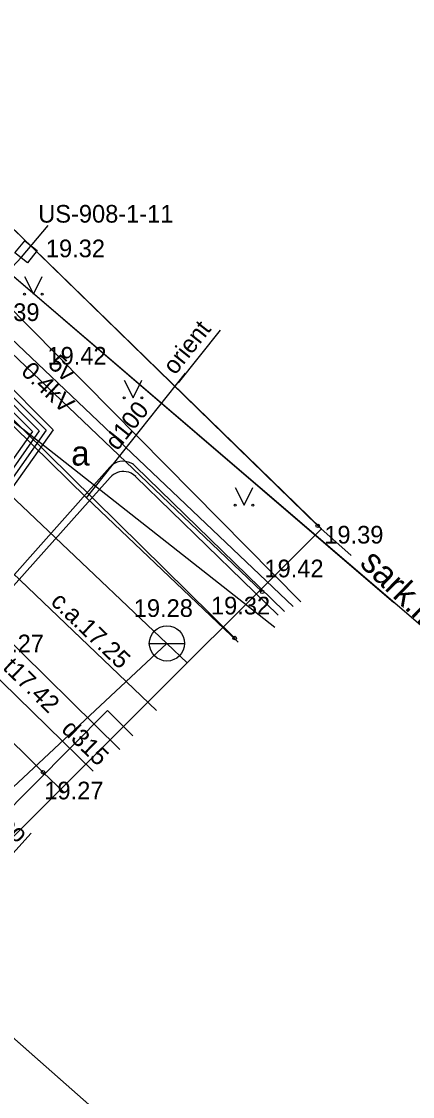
# Model space of a CAD drawing. Extents: x 532933 to 533143, y 328014 to 328163.
# Drawn here: x 533036.51 to 533047.57, y 328096.56 to 328126.98 of the extents above; entities that cross this region are included whole.
import ezdxf

# ---------------------------------------------------------------- set-up
doc = ezdxf.new("R2010")
doc.units = 0
for name, color, linetype in [('APGR_SARK_####_####_#', 7, 'Continuous'), ('APGR_SARK_####_TKST_#', 7, 'Continuous'), ('APGS_VADV_ZSPR_####_#', 7, 'Continuous'), ('APGS_VADV_ZSPR_TKST_#', 7, 'Continuous'), ('CELI_CAPM_####_####_#', 7, 'Continuous'), ('CELI_CMAL_####_####_#', 7, 'Continuous'), ('CELI_CSEG_####_TKST_#', 7, 'Continuous'), ('ELEK_ELEM_####_####_#', 7, 'Continuous'), ('ELEK_ELEM_####_TKST_#', 7, 'Continuous'), ('ELEK_VADP_ZSPR_####_#', 7, 'Continuous'), ('LKAN_ELEM_PAST_TKST_#', 7, 'Continuous'), ('LKAN_VADP_PAST_####_#', 7, 'Continuous'), ('LKAN_VADP_PAST_TKST_#', 7, 'Continuous'), ('NORB_ZOGS_KOKA_####_#', 7, 'Continuous'), ('NORB_ZOGS_ZSTP_####_#', 7, 'Continuous'), ('RAMI_UZMR_####_####_#', 7, 'Continuous'), ('RELJ_AATZ_####_TKST_#', 7, 'Continuous'), ('RELJ_ELEM_####_####_#', 7, 'Continuous'), ('ROBZ_PROJ_####_####_#', 7, 'Continuous'), ('ROBZ_UZMR_####_####_#', 7, 'Continuous'), ('SAKK_IZVK_####_TKST_#', 7, 'Continuous'), ('SAKT_VADP_KABE_####_#', 7, 'Continuous'), ('SAKT_VADV_PKAB_####_#', 7, 'Continuous'), ('SKAN_VADP_PAST_####_#', 7, 'Continuous'), ('TERT_ELEM_####_####_#', 7, 'Continuous'), ('UDTK_ELEM_####_####_#', 7, 'Continuous'), ('UDTK_ELEM_####_TKST_#', 7, 'Continuous'), ('UDTK_VADP_UDEN_####_#', 7, 'Continuous'), ('UDTK_VADP_UDEN_TKST_#', 7, 'Continuous')]:
    doc.layers.add(name, color=color, linetype=linetype)

msp = doc.modelspace()

# ---------------------------------------------------------------- linework, layer by layer
at = {"layer": 'APGR_SARK_####_####_#'}
msp.add_line((533031.763, 328123.637), (533047.049, 328110.542), dxfattribs=at)
at = {"layer": 'APGS_VADV_ZSPR_####_#'}
msp.add_line((533035.157, 328119.006), (533044.195, 328110.43), dxfattribs=at)
at = {"layer": 'CELI_CAPM_####_####_#'}
for points in [[(533042.54, 328109.533), (533031.272, 328120.63), (533030.925, 328121.836)], [(533031.218, 328107.846), (533032.06, 328108.202), (533033.785, 328108.244), (533035.723, 328107.108), (533037.113, 328105.736)], [(533037.113, 328105.736), (533037.712, 328105.165)]]:
    msp.add_lwpolyline(points, dxfattribs=at)
at = {"layer": 'CELI_CMAL_####_####_#'}
msp.add_lwpolyline([(533032.509, 328123.107), (533032.012, 328121.984), (533033.169, 328120.513), (533043.316, 328110.84)], dxfattribs=at)
at = {"layer": 'ELEK_ELEM_####_####_#'}
msp.add_lwpolyline([(533036.673, 328120.155), (533036.322, 328120.433), (533036.596, 328120.778), (533036.946, 328120.5)], close=True, dxfattribs=at)
at = {"layer": 'ELEK_VADP_ZSPR_####_#'}
for p, q in [((533021.678, 328131.149), (533037.401, 328115.43)), ((533021.501, 328130.901), (533037.01, 328115.397)), ((533021.59, 328131.025), (533037.205, 328115.414)), ((533021.413, 328130.777), (533036.815, 328115.38)), ((533036.815, 328115.38), (533032.22, 328108.88)), ((533037.01, 328115.397), (533032.337, 328108.786)), ((533037.205, 328115.414), (533032.454, 328108.692)), ((533037.401, 328115.43), (533032.572, 328108.599)), ((533039.726, 328114.397), (533043.953, 328110.288)), ((533039.737, 328114.107), (533043.774, 328110.183))]:
    msp.add_line(p, q, dxfattribs=at)
for points in [[(533035.235, 328118.966), (533036.504, 328120.317), (533037.265, 328121.207)], [(533035.769, 328110.742), (533039.003, 328114.37)], [(533036.041, 328110.746), (533039.014, 328114.08)]]:
    msp.add_lwpolyline(points, dxfattribs=at)
for centre, start, end in [((533039.378, 328114.039), 61.8983, 138.5412), ((533039.378, 328114.039), 45.8115, 61.8983), ((533039.389, 328113.749), 80.8346, 138.5412), ((533039.389, 328113.749), 45.8115, 80.8346)]:
    msp.add_arc(centre, 0.5, start, end, dxfattribs=at)
at = {"layer": 'LKAN_VADP_PAST_####_#'}
msp.add_lwpolyline([(533000, 328144.172), (533010.252, 328132.804), (533025.892, 328117.826), (533035.077, 328109.135), (533038.53, 328105.77)], dxfattribs=at)
at = {"layer": 'NORB_ZOGS_KOKA_####_#'}
msp.add_line((533045.834, 328111.872), (533044.891, 328112.709), dxfattribs=at)
at = {"layer": 'NORB_ZOGS_ZSTP_####_#'}
msp.add_lwpolyline([(533044.891, 328112.709), (533034.71, 328122.623), (533032.594, 328123.133)], dxfattribs=at)
at = {"layer": 'RAMI_UZMR_####_####_#'}
msp.add_lwpolyline([(532947.854, 328059.458), (532970.012, 328105.269), (532980.164, 328130.66), (532983.041, 328140.509), (533003.397, 328153.917), (533034.71, 328122.623), (533045.001, 328112.629), (533020.332, 328088.009), (533039.378, 328069.977), (533029.682, 328029.753), (533016.724, 328021.343), (532947.854, 328059.458)], dxfattribs=at)
at = {"layer": 'RELJ_ELEM_####_####_#'}
for centre in [(533044.891, 328112.709), (533043.316, 328110.84), (533042.54, 328109.533), (533037.113, 328105.736)]:
    msp.add_circle(centre, 0.05, dxfattribs=at)
at = {"layer": 'ROBZ_PROJ_####_####_#'}
for p, q in [((533031.763, 328123.637), (533050.089, 328107.938)), ((533038.5, 328096.255), (533029.138, 328104.514))]:
    msp.add_line(p, q, dxfattribs=at)
at = {"layer": 'ROBZ_UZMR_####_####_#'}
msp.add_lwpolyline([(533030.97, 328020.652), (533020.389, 328026.352), (533029.157, 328030.58), (533030.421, 328036.082), (533037.903, 328068.645), (533014.917, 328088.072), (533029.138, 328104.514), (533038.98, 328095.831)], dxfattribs=at)
at = {"layer": 'SAKK_IZVK_####_TKST_#'}
msp.add_line((533036.088, 328103.248), (533036.783, 328104.015), dxfattribs=at)
at = {"layer": 'SAKT_VADP_KABE_####_#'}
msp.add_lwpolyline([(533034.149, 328123.442), (533033.94, 328123.175), (533033.696, 328121.399), (533044.408, 328110.556)], dxfattribs=at)
at = {"layer": 'SAKT_VADV_PKAB_####_#'}
msp.add_lwpolyline([(533043.676, 328109.828), (532992.415, 328150.168)], dxfattribs=at)
at = {"layer": 'SKAN_VADP_PAST_####_#'}
msp.add_line((533025.52, 328119.937), (533039.293, 328106.377), dxfattribs=at)
at = {"layer": 'TERT_ELEM_####_####_#'}
for p, q in [((533036.591, 328119.764), (533036.841, 328119.264)), ((533036.841, 328119.264), (533037.091, 328119.764)), ((533039.415, 328116.836), (533039.665, 328116.336)), ((533039.665, 328116.336), (533039.915, 328116.836)), ((533042.555, 328113.796), (533042.805, 328113.296)), ((533042.805, 328113.296), (533043.055, 328113.796))]:
    msp.add_line(p, q, dxfattribs=at)
for centre, radius in [((533036.591, 328119.264), 0.028), ((533037.091, 328119.264), 0.0263), ((533039.415, 328116.335), 0.028), ((533039.915, 328116.335), 0.0263), ((533042.554, 328113.295), 0.028), ((533043.054, 328113.295), 0.0263)]:
    msp.add_circle(centre, radius, dxfattribs=at)
at = {"layer": 'UDTK_ELEM_####_####_#'}
msp.add_line((533040.124, 328109.383), (533041.124, 328109.383), dxfattribs=at)
msp.add_circle((533040.624, 328109.383), 0.5, dxfattribs=at)
at = {"layer": 'UDTK_VADP_UDEN_####_#'}
for p, q in [((533026.302, 328120.883), (533040.325, 328107.485)), ((533040.947, 328116.758), (533042.14, 328118.252)), ((533038.35, 328113.506), (533041.144, 328117.035)), ((533040.624, 328109.383), (533041.198, 328108.834)), ((533038.939, 328107.482), (533011.851, 328080.208)), ((533039.653, 328106.764), (533038.939, 328107.482))]:
    msp.add_line(p, q, dxfattribs=at)
for points in [[(533010.744, 328081.458), (533040.624, 328109.383), (533024.808, 328124.378), (533000, 328150.276)], [(533042.643, 328109.414), (533038.35, 328113.506), (533028.561, 328123.095), (533033.182, 328124.239)]]:
    msp.add_lwpolyline(points, dxfattribs=at)

# ---------------------------------------------------------------- texts
at = {"layer": 'APGR_SARK_####_TKST_#'}
msp.add_text('sark.līn.', height=0.7, rotation=315.8026, dxfattribs=at).set_placement((533046.049, 328111.615))
at = {"layer": 'APGS_VADV_ZSPR_TKST_#'}
for s, p in [('5v', (533037.23, 328117.246)), ('0.4kV', (533036.463, 328117.039))]:
    msp.add_text(s, height=0.5, rotation=316.5034, dxfattribs=at).set_placement(p)
at = {"layer": 'CELI_CSEG_####_TKST_#'}
msp.add_text('a', height=0.7, dxfattribs=at).set_placement((533037.913, 328114.416))
at = {"layer": 'ELEK_ELEM_####_TKST_#'}
msp.add_text('US-908-1-11', height=0.5, dxfattribs=at).set_placement((533036.979, 328121.291))
at = {"layer": 'LKAN_ELEM_PAST_TKST_#'}
msp.add_text(' 19.27', height=0.5, dxfattribs=at).set_placement((533035.282, 328109.131))
at = {"layer": 'LKAN_VADP_PAST_TKST_#'}
for s, p in [('t17.42', (533035.948, 328108.673)), ('d315', (533037.609, 328106.919))]:
    msp.add_text(s, height=0.5, rotation=315.8258, dxfattribs=at).set_placement(p)
at = {"layer": 'RELJ_AATZ_####_TKST_#'}
for s, p in [(' 19.32', (533037.01, 328120.311)), (' 19.39', (533035.157, 328118.506)), ('19.42', (533037.241, 328117.273)), (' 19.39', (533044.891, 328112.209)), (' 19.42', (533043.197, 328111.253)), (' 19.32', (533041.684, 328110.202)), (' 19.27', (533036.967, 328104.968))]:
    msp.add_text(s, height=0.5, dxfattribs=at).set_placement(p)
at = {"layer": 'SAKK_IZVK_####_TKST_#'}
msp.add_text('oo', height=0.5, rotation=317.7972, dxfattribs=at).set_placement((533035.857, 328104.201))
at = {"layer": 'UDTK_ELEM_####_TKST_#'}
msp.add_text(' 19.28', height=0.5, dxfattribs=at).set_placement((533039.498, 328110.132))
at = {"layer": 'UDTK_VADP_UDEN_TKST_#'}
for s, rotation, p in [('orient', 51.63, (533040.855, 328116.956)), ('d100', 51.63, (533039.217, 328114.814)), ('c.a.17.25', 316.3074, (533037.304, 328110.526))]:
    msp.add_text(s, height=0.5, rotation=rotation, dxfattribs=at).set_placement(p)

doc.saveas('drawing.dxf')
